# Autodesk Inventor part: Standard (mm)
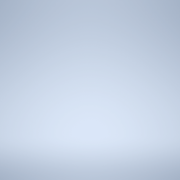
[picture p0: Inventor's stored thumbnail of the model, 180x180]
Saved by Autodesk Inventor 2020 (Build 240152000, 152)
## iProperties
Created: 2019-02
Part Number: Standard (mm)
Material: Ogólny
Document SubType Name: Modeling
Density: 1 g/cm^3
Appearance: Domyślna
Catalog Web Link: www.expertbooks.pl
Designer: F.Stasiak
Manager: www.cadconsulting.pl
Company: Fabian Stasiak CAD Consulting
Subject: Zbiór ćwiczeń. Autodesk Inventor 2020. Kurs Professional
Author: F.Stasiak
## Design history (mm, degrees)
